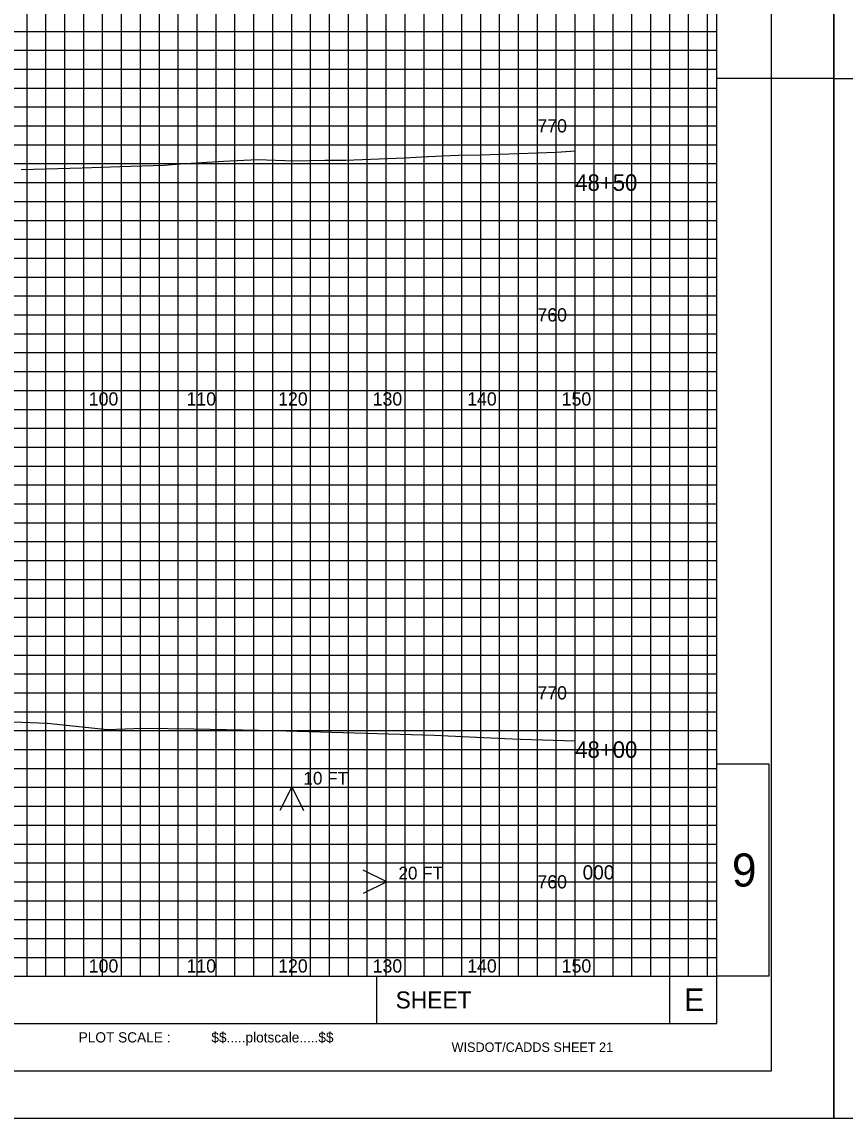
# Model space of a CAD drawing. Extents: x 578243 to 601557, y 174899 to 175559.
# Drawn here: x 600111.3 to 600198.4, y 174898.8 to 175014.8 of the extents above; entities that cross this region are included whole.
import ezdxf

# ---------------------------------------------------------------- set-up
doc = ezdxf.new("R2010")
doc.units = 0
for name, color, linetype in [('E_PROF_Grid', 7, 'Continuous'), ('E_PROF_GridMin', 7, 'Continuous'), ('P_E_XS_Ground', 7, 'Continuous'), ('P_XS_Text', 7, 'Continuous'), ('PLT_Sheet_Border', 7, 'Continuous'), ('PLT_Sheet_Info', 7, 'Continuous')]:
    doc.layers.add(name, color=color, linetype=linetype)

msp = doc.modelspace()

# ---------------------------------------------------------------- linework, layer by layer
at = {"layer": 'E_PROF_Grid'}
for p, q in [((600119.84, 174913.8), (600119.84, 175108.8)), ((600129.84, 174913.8), (600129.84, 175108.8)), ((600139.84, 174913.8), (600139.84, 175108.8)), ((600149.84, 174913.8), (600149.84, 175108.8)), ((600159.84, 174913.8), (600159.84, 175108.8)), ((600169.84, 174913.8), (600169.84, 175108.8)), ((600179.84, 174913.8), (600179.84, 175108.8)), ((599869.84, 175013.8), (600184.84, 175013.8)), ((599869.84, 175003.8), (600184.84, 175003.8)), ((599869.84, 174993.8), (600184.84, 174993.8)), ((599869.84, 174983.8), (600184.84, 174983.8)), ((599869.84, 174973.8), (600184.84, 174973.8)), ((599869.84, 174963.8), (600184.84, 174963.8)), ((599869.84, 174953.8), (600184.84, 174953.8)), ((599869.84, 174943.8), (600184.84, 174943.8)), ((599869.84, 174933.8), (600184.84, 174933.8)), ((599869.84, 174923.8), (600184.84, 174923.8))]:
    msp.add_line(p, q, dxfattribs=at)
at = {"layer": 'E_PROF_GridMin'}
for p, q in [((600111.84, 174913.8), (600111.84, 175108.8)), ((600113.84, 174913.8), (600113.84, 175108.8)), ((600115.84, 174913.8), (600115.84, 175108.8)), ((600117.84, 174913.8), (600117.84, 175108.8)), ((600121.84, 174913.8), (600121.84, 175108.8)), ((600123.84, 174913.8), (600123.84, 175108.8)), ((600125.84, 174913.8), (600125.84, 175108.8)), ((600127.84, 174913.8), (600127.84, 175108.8)), ((600131.84, 174913.8), (600131.84, 175108.8)), ((600133.84, 174913.8), (600133.84, 175108.8)), ((600135.84, 174913.8), (600135.84, 175108.8)), ((600137.84, 174913.8), (600137.84, 175108.8)), ((600141.84, 174913.8), (600141.84, 175108.8)), ((600143.84, 174913.8), (600143.84, 175108.8)), ((600145.84, 174913.8), (600145.84, 175108.8)), ((600147.84, 174913.8), (600147.84, 175108.8)), ((600151.84, 174913.8), (600151.84, 175108.8)), ((600153.84, 174913.8), (600153.84, 175108.8)), ((600155.84, 174913.8), (600155.84, 175108.8)), ((600157.84, 174913.8), (600157.84, 175108.8)), ((600161.84, 174913.8), (600161.84, 175108.8)), ((600163.84, 174913.8), (600163.84, 175108.8)), ((600165.84, 174913.8), (600165.84, 175108.8)), ((600167.84, 174913.8), (600167.84, 175108.8)), ((600171.84, 174913.8), (600171.84, 175108.8)), ((600173.84, 174913.8), (600173.84, 175108.8)), ((600175.84, 174913.8), (600175.84, 175108.8)), ((600177.84, 174913.8), (600177.84, 175108.8)), ((600181.84, 174913.8), (600181.84, 175108.8)), ((600183.84, 174913.8), (600183.84, 175108.8)), ((599869.84, 175011.8), (600184.84, 175011.8)), ((599869.84, 175009.8), (600184.84, 175009.8)), ((599869.84, 175007.8), (600184.84, 175007.8)), ((599869.84, 175005.8), (600184.84, 175005.8)), ((599869.84, 175001.8), (600184.84, 175001.8)), ((599869.84, 174999.8), (600184.84, 174999.8)), ((599869.84, 174997.8), (600184.84, 174997.8)), ((599869.84, 174995.8), (600184.84, 174995.8)), ((599869.84, 174991.8), (600184.84, 174991.8)), ((599869.84, 174989.8), (600184.84, 174989.8)), ((599869.84, 174987.8), (600184.84, 174987.8)), ((599869.84, 174985.8), (600184.84, 174985.8)), ((599869.84, 174981.8), (600184.84, 174981.8)), ((599869.84, 174979.8), (600184.84, 174979.8)), ((599869.84, 174977.8), (600184.84, 174977.8)), ((599869.84, 174975.8), (600184.84, 174975.8)), ((599869.84, 174971.8), (600184.84, 174971.8)), ((599869.84, 174969.8), (600184.84, 174969.8)), ((599869.84, 174967.8), (600184.84, 174967.8)), ((599869.84, 174965.8), (600184.84, 174965.8)), ((599869.84, 174961.8), (600184.84, 174961.8)), ((599869.84, 174959.8), (600184.84, 174959.8)), ((599869.84, 174957.8), (600184.84, 174957.8)), ((599869.84, 174955.8), (600184.84, 174955.8)), ((599869.84, 174951.8), (600184.84, 174951.8)), ((599869.84, 174949.8), (600184.84, 174949.8)), ((599869.84, 174947.8), (600184.84, 174947.8)), ((599869.84, 174945.8), (600184.84, 174945.8)), ((599869.84, 174941.8), (600184.84, 174941.8)), ((599869.84, 174939.8), (600184.84, 174939.8)), ((599869.84, 174937.8), (600184.84, 174937.8)), ((599869.84, 174935.8), (600184.84, 174935.8)), ((599869.84, 174931.8), (600184.84, 174931.8)), ((599869.84, 174929.8), (600184.84, 174929.8)), ((599869.84, 174927.8), (600184.84, 174927.8)), ((599869.84, 174925.8), (600184.84, 174925.8)), ((599869.84, 174921.8), (600184.84, 174921.8)), ((599869.84, 174919.8), (600184.84, 174919.8)), ((599869.84, 174917.8), (600184.84, 174917.8)), ((599869.84, 174915.8), (600184.84, 174915.8)), ((600197.19, 174898.8), (600197.19, 174908.8)), ((600187.19, 174898.8), (600197.19, 174898.8))]:
    msp.add_line(p, q, dxfattribs=at)
at = {"layer": 'P_E_XS_Ground'}
for points in [[(600111.23, 174999.19), (600117.66, 174999.37), (600119.69, 174999.44), (600121.66, 174999.49), (600126.36, 174999.63), (600128.03, 174999.77), (600132.64, 175000.05), (600136.23, 175000.24), (600140.08, 175000.11), (600143.34, 175000.16), (600145.55, 175000.16), (600151.79, 175000.41), (600154.24, 175000.56), (600157.45, 175000.7), (600159.8, 175000.75), (600167.86, 175001), (600169.84, 175001.16)], [(600107.69, 174940.82), (600113.97, 174940.58), (600120.34, 174939.92), (600124.09, 174940.06), (600129.48, 174939.99), (600138.07, 174939.81), (600154.92, 174939.31), (600162.4, 174938.96), (600164.06, 174938.91), (600169.84, 174938.73)]]:
    msp.add_lwpolyline(points, dxfattribs=at)
at = {"layer": 'PLT_Sheet_Border'}
for points in [[(599857.19, 174898.8), (600197.19, 174898.8), (600197.19, 175118.8), (599857.19, 175118.8)], [(600197.19, 174898.8), (600537.19, 174898.8), (600537.19, 175118.8), (600197.19, 175118.8)], [(599859.59, 174903.8), (600190.59, 174903.8), (600190.59, 175113.8), (599859.59, 175113.8)]]:
    msp.add_lwpolyline(points, close=True, dxfattribs=at)
at = {"layer": 'PLT_Sheet_Info'}
for p, q in [((600184.84, 174908.8), (600184.84, 175108.8)), ((600197.19, 175003.8), (600197.19, 175013.8)), ((600197.19, 175003.8), (600197.19, 175013.8)), ((600197.19, 175008.8), (600184.84, 175008.8)), ((600197.19, 175008.8), (600209.84, 175008.8)), ((599869.84, 174913.8), (600184.84, 174913.8)), ((600148.84, 174908.8), (600148.84, 174913.8)), ((600179.84, 174908.8), (600179.84, 174913.8)), ((599869.84, 174908.8), (600184.84, 174908.8)), ((600197.19, 174898.8), (600197.19, 174908.8)), ((600197.19, 174898.8), (600207.19, 174898.8))]:
    msp.add_line(p, q, dxfattribs=at)
msp.add_lwpolyline([(600184.84, 174936.3), (600190.34, 174936.3), (600190.34, 174913.8), (600184.84, 174913.8)], close=True, dxfattribs=at)
for points in [[(600139.84, 174933.84), (600138.6, 174931.36)], [(600139.84, 174923.8), (600139.84, 174933.84), (600141.08, 174931.36)], [(600149.89, 174923.8), (600147.4, 174925.04)], [(600139.84, 174923.8), (600149.89, 174923.8), (600147.4, 174922.55)]]:
    msp.add_lwpolyline(points, dxfattribs=at)

# ---------------------------------------------------------------- texts
at = {"layer": 'P_XS_Text'}
for s, height, p in [('770', 1.4, (600165.84, 175003.1)), ('48+50', 1.75, (600169.84, 174996.92)), ('760', 1.4, (600165.84, 174983.1)), ('100', 1.4, (600118.37, 174974.2)), ('110', 1.4, (600128.71, 174974.2)), ('120', 1.4, (600138.41, 174974.2)), ('130', 1.4, (600148.41, 174974.2)), ('140', 1.4, (600158.41, 174974.2)), ('150', 1.4, (600168.41, 174974.2)), ('770', 1.4, (600165.84, 174943.1)), ('48+00', 1.75, (600169.84, 174936.92)), ('760', 1.4, (600165.84, 174923.1)), ('100', 1.4, (600118.37, 174914.2)), ('110', 1.4, (600128.71, 174914.2)), ('120', 1.4, (600138.41, 174914.2)), ('130', 1.4, (600148.41, 174914.2)), ('140', 1.4, (600158.41, 174914.2)), ('150', 1.4, (600168.41, 174914.2))]:
    msp.add_text(s, height=height, rotation=360, dxfattribs=at).set_placement(p)
at = {"layer": 'PLT_Sheet_Info'}
for s, height, p in [('  10 FT', 1.347, (600140.09, 174934.09)), ('9', 3.5, (600186.42, 174923.3)), ('  20 FT', 1.347, (600150.14, 174924.05)), ('     000', 1.5, (600167.84, 174924.05)), ('SHEET ', 1.8, (600150.84, 174910.4)), ('E', 2.4, (600181.36, 174910.12)), ('PLOT SCALE : ', 1.08, (600117.3, 174906.8)), ('$$.....plotscale.....$$', 1.08, (600131.34, 174906.8)), ('WISDOT/CADDS SHEET 21', 1, (600156.76, 174905.8))]:
    msp.add_text(s, height=height, dxfattribs=at).set_placement(p)

doc.saveas('drawing.dxf')
